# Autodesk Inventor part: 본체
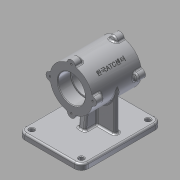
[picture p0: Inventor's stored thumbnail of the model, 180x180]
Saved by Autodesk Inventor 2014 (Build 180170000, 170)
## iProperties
Created: 2015-12
Part Number: 본체
Material: 알루미늄 6061
Document SubType Name: Modeling
Designer: L-10
Density: 2.71 g/cm^3
Appearance: 알루미늄 - 평지
Mass: 1164.68 g
Surface Area: 816.39 cm^2
Volume: 429.772 cm^3
Author: L-10
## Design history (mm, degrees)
sketch "스케치1"
  geometry: L1 (37, 42.5)-(0, 42.5); L2 (0, 42.5)-(0, 0); L3 (0, 0)-(37, 0); L4 (37, 0)-(37, 42.5); 1 further point
  constraints: 8 end point, 2 parallel, 1 coincident, 1 horizontal, 1 perpendicular
  dimensions: "d2" = 74 diameter of L4 L2; "d3" = 42.5 distance of L3.end L1.start
revolve "회전1" sketch "스케치1" stored, may be unused: angle "d4" = 90 deg
hole "구멍1" diameter "d7" = 42; stored, may be unused: countersink angle "d11" = 90 deg, drill point angle "d13" = 0 deg; dims "d5" = 10, "d6" = 10, "d8" = 6, "d9" = 47, "d10" = 22, "d12" = 42.5
sketch "스케치2"
  geometry: L1 (-37, 42.5)-(37, 42.5) reference; L2 (37, 42.5)-(37, 0) reference; L3 (37, 42.5)-(44, 42.5); L4 (44, 42.5)-(44, 30.048); L5 (44, 30.048)-(37, 27.5); L6 (37, 42.5)-(37, 27.5); 1 further point
  constraints: 8 end point, 2 perpendicular, 1 collinear, 1 point on line
  dimensions: "d14" = 110 deg angle of L2 L5; "d15" = 15 distance from line of L5.end L3; "d16" = 7 distance of L2.start L3.end
revolve "회전2" sketch "스케치2" stored, may be unused: angle "d17" = 90 deg
hole "구멍3" diameter "d29" = 3.242; stored, may be unused: countersink angle "d33" = 90 deg, drill point angle "d35" = 118 deg; dims "d27" = 10, "d28" = 10, "d30" = 9, "d31" = 47, "d32" = 22, "d34" = 11
fillet "모깎기1" dims "d36" = 3
node "작업 평면1"
sketch "스케치3"
  geometry: L1 (55, 80)-(-55, 80); L2 (-55, 80)-(-55, -60); L3 (-55, -60)-(55, -60); L4 (55, -60)-(55, 80); 2 further points
  constraints: 8 end point, 2 parallel, 1 horizontal, 1 midpoint, 1 perpendicular, 1 vertical alignment
  dimensions: "d41" = 140 distance of L3.end L1.start; "d42" = 110 distance of L2.end L3.end; "d43" = 80 distance from line of point (0, 0) L1
extrude "돌출1" join sketch "스케치3" distance "d44" = 10; taper "d45" = 0 deg
sketch "스케치4"
  geometry: L1 (-37, -4)-(37, -4); L2 (37, -4)-(37, 4); L3 (37, 4)-(-37, 4); L4 (-37, 4)-(-37, -4); 3 further points
  constraints: 8 end point, 2 midpoint, 2 parallel, 1 horizontal, 1 horizontal alignment, 1 perpendicular, 1 vertical alignment
  dimensions: "d46" = 8 distance of L3.end L1.start; "d47" = 74 distance of L2.end L3.end
extrude "돌출2" join sketch "스케치4" stored distance "d48" = 10; taper "d49" = 0 deg
sketch "스케치5"
  geometry: L1 (-37, 25.399)-(-37, -25.399) reference; L2 (-70, 4)-(0, 4) reference; L3 (-70, -60)-(-70, 80) reference; L4 (-37, 20.948)-(-70, 25); 1 further point
  constraints: 2 end point, 2 point on line
  dimensions: "d50" = 97 deg angle of L3 L4; "d51" = 25 vertical distance of point (0, 0) L4.end
feature "리브1" sketch "스케치5" dims "d52" = 1, "d53" = 12, "d54" = 0, "d55" = 0, "d56" = 1, "d57" = 1
fillet "모깎기2" dims "d58" = 12
sketch "스케치6"
  geometry: L1 (-55, 48)-(-55, -68) reference; L2 (43, 60)-(-43, 60) reference; L3 (-43, -68)-(43, -68); L4 (43, -68)-(43, 48); L5 (43, 48)-(-43, 48); L6 (-43, 48)-(-43, -68); 9 further points
  constraints: 8 end point, 4 coincident, 4 midpoint, 2 parallel, 1 horizontal, 1 horizontal alignment, 1 perpendicular, 1 vertical alignment
  dimensions: "d59" = 116 distance of L5.end L3.start; "d60" = 86 distance of L3.start L3.end
hole "구멍4" sketch "스케치6" at (-43, -68), (43, -68), (43, 48), (-43, 48) diameter "d61" = 8; stored, may be unused: countersink angle "d65" = 90 deg, drill point angle "d67" = 0 deg; dims "d62" = 9, "d63" = 47, "d64" = 22, "d66" = 11
chamfer "모따기1" distance "d68" = 1; stored, may be unused: second distance "d69" = 2, angle "d70" = 45 deg
chamfer "모따기2" distance "d71" = 1; stored, may be unused: second distance "d72" = 2, angle "d73" = 45 deg
chamfer "모따기3" distance "d74" = 1; stored, may be unused: second distance "d75" = 2, angle "d76" = 45 deg
chamfer "모따기4" distance "d77" = 1; stored, may be unused: second distance "d78" = 2, angle "d79" = 45 deg
fillet "모깎기3" dims "d80" = 3
fillet "모깎기4" dims "d81" = 3
sketch "스케치7"
  geometry: L1 (0, 0)-(26.163, 26.163); L2 (-77, 0)-(77, 0) reference; A1 r 37 centre (0, 0) between (35.863, 9.104) and (9.104, 35.863) reference; 1 further point
  constraints: 2 end point, 1 coincident, 1 point on circle
  dimensions: "d82" = 45 deg angle of L2 L1
node "작업 평면2"
sketch "스케치8"
  geometry: L1 (-18.921, 42.5)-(18.921, 42.5) reference; 2 further points
  constraints: 1 coincident, 1 other
  dimensions: "d83" = 42.5 distance from line of point (0, 0) L1
feature "엠보싱1" sketch "스케치8" dims "d2" = 74, "d3" = 42.5, "d84" = 0.5, "d85" = 0
chamfer "모따기5" distance "d86" = 1; stored, may be unused: second distance "d87" = 2, angle "d88" = 45 deg
chamfer "모따기6" distance "d89" = 1; stored, may be unused: second distance "d90" = 2, angle "d91" = 45 deg
fillet "모깎기5" dims "d92" = 0.3
node "솔리드1"
pattern_circular "원형 패턴1" dims "d38" = 360 deg
mirror "대칭1"
mirror "대칭2"
